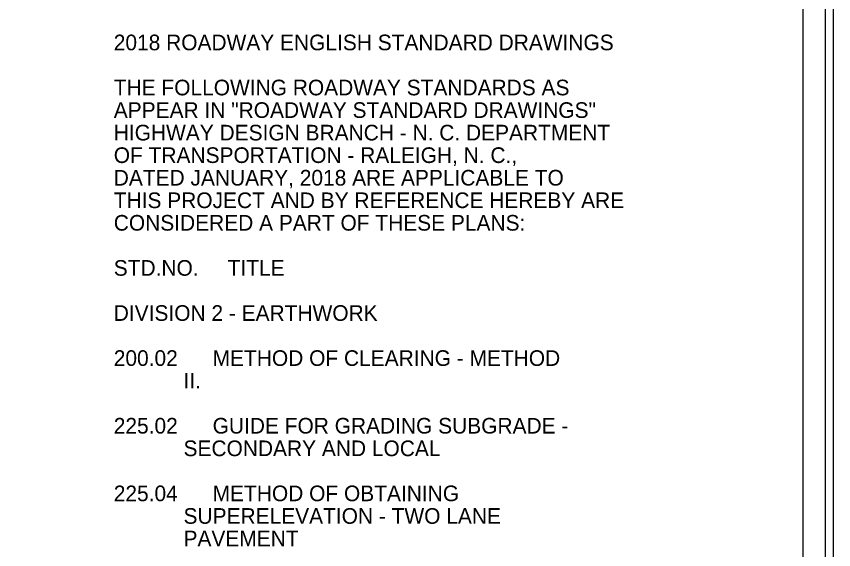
# Model space of a CAD drawing. Extents: x 2486563 to 2488026, y 371425 to 372193.
# Drawn here: x 2487286.5 to 2487469.3, y 371948.5 to 372067.8 of the extents above; entities that cross this region are included whole.
import ezdxf

# ---------------------------------------------------------------- set-up
doc = ezdxf.new("R2010")
doc.units = 0
for name, color, linetype in [('Sheet Plan CELL', 7, 'Continuous'), ('Sheet Plot Border Inside CELL', 7, 'Continuous'), ('Sheet Plot Border Outside CELL', 7, 'Continuous'), ('Text', 7, 'Continuous')]:
    doc.layers.add(name, color=color, linetype=linetype)

msp = doc.modelspace()

# ---------------------------------------------------------------- linework, layer by layer
at = {"layer": 'Sheet Plan CELL'}
msp.add_lwpolyline([(2487462.49, 372136.11), (2486862.49, 372136.11), (2486862.49, 371716.11), (2487462.49, 371716.11)], close=True, dxfattribs=at)
at = {"layer": 'Sheet Plot Border Inside CELL'}
msp.add_lwpolyline([(2486801.09, 371715.11), (2487467.49, 371715.11), (2487467.49, 372137.11), (2486801.09, 372137.11)], close=True, dxfattribs=at)
at = {"layer": 'Sheet Plot Border Outside CELL'}
msp.add_lwpolyline([(2486795.89, 371707.11), (2487469.29, 371707.11), (2487469.29, 372145.11), (2486795.89, 372145.11)], close=True, dxfattribs=at)

# ---------------------------------------------------------------- texts
at = {"layer": 'Text'}
for s, p in [('2018 ROADWAY ENGLISH STANDARD DRAWINGS', (2487308.26, 372060.19)), ('THE FOLLOWING ROADWAY STANDARDS AS ', (2487308.26, 372050.11)), ('APPEAR IN "ROADWAY STANDARD DRAWINGS" ', (2487308.26, 372045.06)), ('HIGHWAY DESIGN BRANCH - N. C. DEPARTMENT ', (2487308.26, 372040.02)), ('OF TRANSPORTATION - RALEIGH, N. C., ', (2487308.26, 372034.98)), ('DATED JANUARY, 2018 ARE APPLICABLE TO ', (2487308.26, 372029.93)), ('THIS PROJECT AND BY REFERENCE HEREBY ARE ', (2487308.26, 372024.89)), ('CONSIDERED A PART OF THESE PLANS:', (2487308.26, 372019.85)), ('STD.NO.     TITLE', (2487308.26, 372009.76)), ('DIVISION 2 - EARTHWORK', (2487308.26, 371999.67)), ('200.02      METHOD OF CLEARING - METHOD ', (2487308.26, 371989.59)), ('            II. ', (2487308.26, 371984.54)), ('225.02      GUIDE FOR GRADING SUBGRADE - ', (2487308.26, 371974.46)), ('            SECONDARY AND LOCAL', (2487308.26, 371969.41)), ('225.04      METHOD OF OBTAINING    ', (2487308.26, 371959.33)), ('            SUPERELEVATION - TWO LANE', (2487308.26, 371954.28)), ('            PAVEMENT', (2487308.26, 371949.24))]:
    msp.add_text(s, height=3.5, dxfattribs=at).set_placement(p)

doc.saveas('drawing.dxf')
